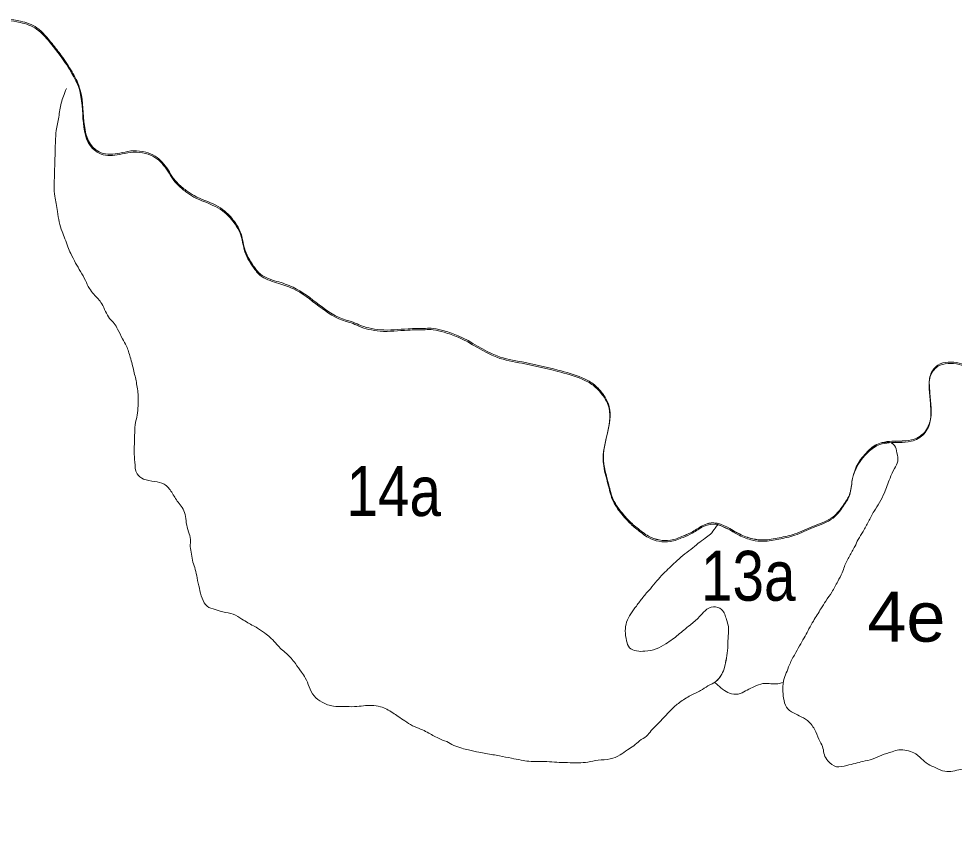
# Model space of a CAD drawing. Extents: x 854879 to 917879, y 8541948 to 8631048.
# Drawn here: x 882670 to 889796, y 8606564 to 8612725 of the extents above; entities that cross this region are included whole.
import ezdxf
from ezdxf.enums import TextEntityAlignment as Align

# ---------------------------------------------------------------- set-up
doc = ezdxf.new("R2010")
doc.units = 0
doc.header["$LTSCALE"] = 150
for name, color, linetype, lineweight in [('12', 7, 'Continuous', 13), ('40', 7, 'Continuous', 13), ('50', 7, 'Continuous', 13), ('59', 7, 'Continuous', 13)]:
    doc.layers.add(name, color=color, linetype=linetype, lineweight=lineweight)

msp = doc.modelspace()

# ---------------------------------------------------------------- linework, layer by layer
at = {"layer": '12'}
for points in [[(883458.2, 8611696.1), (883312.8, 8611690.2), (883254.5, 8611718.9), (883130.1, 8612194.4), (883075.4, 8612309.7), (882992.8, 8612435.6), (882922.5, 8612525.6), (882806.7, 8612646.7), (882682.3, 8612696.7), (882478.6, 8612709.3), (882317.4, 8612665.3), (882183, 8612509), (882088.6, 8612290.9), (882014.9, 8612093.1), (881954.6, 8611953.6), (881858.8, 8611827.3), (881770.9, 8611726.5), (881683.5, 8611663.8), (881605.9, 8611573), (881515, 8611428.8), (881452.8, 8611342.9), (881245.3, 8611256.2), (880823.3, 8611380.8), (880472, 8611369.8)], [(892672.9, 8609465.7), (892198, 8609621.7), (891998.2, 8609756.6), (891869.6, 8609877.9), (891760.9, 8609948), (891672, 8609974.5), (891475.1, 8609928.5), (891429, 8609908.6), (891359.8, 8609878.9), (891318.7, 8609853.9), (891241.9, 8609826.8), (891167.7, 8609799.7), (891085.8, 8609777.7), (890871.6, 8609770.1), (890792.6, 8609771), (890700.8, 8609772.1), (890588.7, 8609778.5), (890319.2, 8609835.3), (890207.7, 8609892.7), (889977.6, 8610050.9), (889903.9, 8610074.7), (889832.8, 8610093.4), (889748.7, 8610102), (889669.4, 8610077.5), (889612.4, 8610001.7), (889606.1, 8609899.9), (889615, 8609790.2), (889613.5, 8609665.3), (889566.5, 8609566.5), (889468.9, 8609509.1), (889374.5, 8609500), (889229, 8609483.9), (889139.1, 8609426.4), (889019.3, 8609216.3), (889000.1, 8609104.4), (888948.1, 8609010.8), (888873.1, 8608925), (888721.8, 8608852.9), (888580.9, 8608793.4), (888460.8, 8608764.3), (888340.7, 8608747.9), (888259.3, 8608756.5), (888157.7, 8608793.4), (887962.4, 8608877.3), (887885.8, 8608860.4), (887801, 8608810.4), (887731.8, 8608778.1), (887632, 8608746.2), (887466.7, 8608776.2), (887378.2, 8608841), (887340.3, 8608872), (887274.9, 8608941.6), (887197.2, 8609054.6), (887162.8, 8609167.2), (887122, 8609379.2), (887160, 8609783.9), (887115, 8609863.4), (887044.5, 8609935.6), (886960.9, 8609982.5), (886775.5, 8610040.8), (886503.5, 8610102.6), (886312.8, 8610148.2), (886016.4, 8610302.1), (885909.8, 8610339.1), (885825.9, 8610357.9), (885767.2, 8610358.6), (885634.6, 8610355.1), (885423, 8610347.5), (885336.5, 8610361.2), (885260.2, 8610385.1), (885201.9, 8610411.3), (885163.8, 8610421.9), (884758.9, 8610671.4), (884634.5, 8610716.2), (884510.2, 8610771.2), (884457.5, 8610833), (884387.7, 8610968.9), (884375.6, 8611025.1), (884356, 8611094.1), (884318.6, 8611160.8), (884238.1, 8611251), (884169.8, 8611295.1), (884004.9, 8611368.5), (883944.2, 8611407.4), (883908.9, 8611435.9), (883845.9, 8611502.9), (883805.9, 8611564.5), (883707.7, 8611670.2), (883636.7, 8611699), (883542.5, 8611710.4), (883458.2, 8611696.1)]]:
    msp.add_spline(points, degree=3, dxfattribs=at)
at = {"layer": '40'}
msp.add_line((887996.2, 8608876.2), (887978, 8608882.8), dxfattribs=at)
for points in [[(883033, 8612194.2), (883011.5, 8612135.1), (882994.2, 8612083.9), (882975.3, 8611977.1), (882956.5, 8611874.2), (882950, 8611791), (882948.3, 8611731.4), (882946.2, 8611664), (882944.3, 8611600.5), (882942.5, 8611536.9), (882939.8, 8611449.6), (882945.5, 8611374), (882955.6, 8611318.2), (882965.7, 8611258.4), (882979, 8611178.7), (883000.5, 8611106.7), (883022.5, 8611050.6), (883044.3, 8610990.5), (883066.4, 8610938.3), (883103.7, 8610866), (883141.1, 8610801.6), (883178.5, 8610733.2), (883208.2, 8610673), (883242.3, 8610628.5), (883303.2, 8610555.6), (883362.9, 8610443.1), (883397.2, 8610406.6), (883423.5, 8610362.3), (883460.7, 8610289.9), (883490.6, 8610233.6), (883519.6, 8610149.6), (883547.8, 8610041.7), (883568.6, 8609945.9), (883581.3, 8609842.3), (883579.4, 8609778.8), (883573.3, 8609707.5), (883559.9, 8609652.2), (883553.7, 8609576.8), (883551, 8609485.6), (883549.3, 8609430), (883554.8, 8609350.4), (883571.9, 8609262.7), (883621.9, 8609221.8), (883704.1, 8609204), (883778.3, 8609182.5), (883835.6, 8609121.6), (883884.5, 8609045), (883914.8, 8609004.6), (883936.9, 8608952.5), (883946.8, 8608888.7), (883964.5, 8608820.8), (883978.4, 8608760.9), (883976.9, 8608709.3), (883986.9, 8608649.5), (883997, 8608589.7), (884015, 8608533.7), (884028.8, 8608469.8), (884046.2, 8608390), (884067.5, 8608314), (884105.1, 8608253.6), (884167.4, 8608228.3), (884226, 8608211.1), (884304.2, 8608193.5), (884370.1, 8608156.2), (884416.5, 8608127.4), (884497.9, 8608081.8), (884555.8, 8608040.8), (884594.2, 8608008.1), (884636.2, 8607963.5), (884670.5, 8607927), (884709, 8607894.3), (884777.6, 8607817.3), (884822.9, 8607752.7), (884853.1, 8607708.3), (884882.6, 8607640.2), (884920, 8607571.8), (884981.5, 8607522.7), (885067.3, 8607493), (885146, 8607491.2), (885228.7, 8607489.3), (885295.9, 8607495.7), (885359, 8607498.3), (885425.7, 8607488.8), (885518.8, 8607443), (885561.3, 8607414.2), (885611.6, 8607381.3), (885669.5, 8607344.2), (885731.8, 8607319), (885782.3, 8607294), (885867.6, 8607248.4), (885929.9, 8607223.2)], [(883459.9, 8611706.3), (883314.5, 8611700.4), (883256.2, 8611729.2), (883131.8, 8612204.6), (883110.6, 8612253.5)], [(887978, 8608882.8), (887964.1, 8608887.6), (887887.5, 8608870.6), (887802.7, 8608820.7), (887733.5, 8608788.4), (887633.7, 8608756.5), (887468.4, 8608786.5), (887379.9, 8608851.2), (887342, 8608882.3), (887276.6, 8608951.8), (887198.9, 8609064.9), (887164.6, 8609177.4), (887123.7, 8609389.4), (887161.7, 8609794.2), (887116.7, 8609873.7), (887046.2, 8609945.9), (886962.6, 8609992.8), (886777.2, 8610051), (886505.2, 8610112.9), (886314.5, 8610158.5), (886018.1, 8610312.4), (885911.5, 8610349.3), (885827.6, 8610368.2), (885769, 8610368.9), (885636.3, 8610365.4), (885424.7, 8610357.7), (885338.2, 8610371.5), (885262, 8610395.3), (885203.6, 8610421.5), (885165.5, 8610432.2), (884760.6, 8610681.7), (884636.2, 8610726.5), (884512, 8610781.5), (884459.2, 8610843.3), (884389.4, 8610979.2), (884377.3, 8611035.4), (884357.7, 8611104.4), (884320.3, 8611171.1), (884239.8, 8611261.3), (884171.5, 8611305.4), (884006.6, 8611378.7), (883945.9, 8611417.7), (883910.6, 8611446.1), (883847.6, 8611513.1), (883807.6, 8611574.8), (883709.4, 8611680.4), (883638.4, 8611709.3), (883544.2, 8611720.6), (883459.9, 8611706.3)], [(890318.5, 8609846.4), (890209.4, 8609902.9), (889979.3, 8610061.1), (889905.6, 8610084.9), (889834.5, 8610103.6), (889750.4, 8610112.3), (889671.1, 8610087.8), (889614.1, 8610012), (889607.8, 8609910.1), (889616.7, 8609800.5), (889615.2, 8609675.6), (889568.2, 8609576.8), (889470.6, 8609519.3), (889376.2, 8609510.3), (889350.9, 8609507.7)], [(889319.9, 8609496.3), (889341.7, 8609477.2), (889359.8, 8609421.1), (889365.8, 8609357.4), (889340.5, 8609302.4), (889306.7, 8609227.7), (889264, 8609117.5), (889226.4, 8609042.9), (889185, 8608976.3), (889143.2, 8608897.8), (889101.6, 8608823.3), (889064.3, 8608760.6), (889039.1, 8608709.5), (888997.5, 8608635), (888959.7, 8608556.4), (888942.6, 8608509.1), (888909, 8608442.4), (888863.2, 8608360), (888817.9, 8608293.5), (888780.7, 8608234.8), (888722.8, 8608140.8), (888689.5, 8608081.9), (888660.3, 8608027), (888627, 8607968.2), (888589.6, 8607901.5), (888547.8, 8607823), (888522.3, 8607760.1), (888501, 8607704.9), (888490.6, 8607621.8), (888496.5, 8607554.1), (888518.1, 8607486.1), (888571.9, 8607441.2), (888630.1, 8607412.1), (888691.9, 8607370.9), (888741, 8607298.3), (888774.1, 8607222.1), (888796.3, 8607173.9), (888806.6, 8607122.1), (888832.9, 8607077.8), (888898.5, 8607032.6), (888977.6, 8607042.7), (889041.1, 8607057.2), (889100.6, 8607071.7), (889172, 8607089.9), (889243.8, 8607120.1), (889323.4, 8607146.1), (889375.1, 8607160.8), (889434, 8607155.5), (889488.6, 8607138.3), (889546.4, 8607093.3), (889596.4, 8607052.5), (889654.6, 8607023.4), (889724.8, 8606997.9), (889847.3, 8607011), (889906.3, 8607009.7), (889948, 8606953.2), (889954.2, 8606897.4), (889955.9, 8606821.9), (889950, 8606758.5), (889932.3, 8606691.4), (889930, 8606615.9), (889928.1, 8606552.4), (889951.7, 8606416.9), (889965.8, 8606360.9), (889983.9, 8606308.9), (890018, 8606264.4), (890071.7, 8606215.5), (890153.8, 8606193.8), (890213, 8606196.4), (890292.1, 8606206.6), (890347.3, 8606209.3), (890430.4, 8606223.3), (890488.2, 8606178.3), (890521.1, 8606094.1), (890527.2, 8606034.4), (890540.8, 8605962.6), (890550.6, 8605894.8), (890580.2, 8605830.6), (890598.3, 8605774.6), (890644.3, 8605733.8), (890706.6, 8605708.6), (890812.7, 8605698.2), (890899.9, 8605716.1), (890987.8, 8605757.8), (891047.8, 8605788.2), (891104, 8605822.7), (891152.4, 8605861.3), (891197, 8605904)], [(885929.9, 8607223.2), (885984.2, 8607194.1), (886046.6, 8607172.8), (886097.4, 8607159.8), (886175.6, 8607142.1), (886281.5, 8607123.8), (886332.4, 8607114.7), (886422.5, 8607096.8), (886496.9, 8607083.2), (886555.7, 8607073.9), (886630.5, 8607072.2), (886713.2, 8607070.3), (886787.9, 8607064.6), (886870.6, 8607062.8), (886933.6, 8607061.3), (887004.7, 8607067.7), (887083.9, 8607081.8), (887174.8, 8607091.6), (887250.5, 8607121.7), (887306.8, 8607160.1), (887355, 8607190.8), (887399.5, 8607229.5), (887451.7, 8607264.1), (887488.5, 8607306.9), (887541.3, 8607361.3), (887582, 8607404.1), (887639, 8607466.3), (887703.6, 8607520.5), (887788, 8607574.2), (887863.9, 8607612.2), (887920.1, 8607646.6), (887980.2, 8607681), (888025.2, 8607735.6), (888046.6, 8607790.7), (888060.4, 8607857.9), (888070.6, 8607937.1), (888072.3, 8607992.7), (888075.3, 8608095.9), (888061.3, 8608151.8), (888024.1, 8608228.1), (887961.8, 8608249.4), (887897.8, 8608219.1), (887853.1, 8608172.4), (887784.3, 8608110.4), (887735.8, 8608071.8), (887651, 8608002.3), (887598.8, 8607967.7), (887526.7, 8607929.6), (887439.5, 8607911.7), (887376.6, 8607913.2), (887322.2, 8607938.2), (887300.1, 8607990.4), (887290.5, 8608066.1), (887300.4, 8608133.4), (887374.9, 8608254.8), (887424.2, 8608321.2), (887481.3, 8608387.4), (887530.3, 8608445.9), (887579.2, 8608500.4), (887627.9, 8608546.9), (887672.5, 8608589.6), (887729.2, 8608640), (887789.6, 8608686.2), (887846.2, 8608732.6), (887898.5, 8608771.2), (887938.8, 8608802), (887975.7, 8608848.8), (887996.2, 8608876.2)]]:
    msp.add_spline(points, degree=3, dxfattribs=at)
at = {"layer": '50'}
msp.add_line((889316.9, 8609498.1), (889290.9, 8609501.3), dxfattribs=at)
for points in [[(883459.9, 8611706.3), (883314.5, 8611700.4), (883256.2, 8611729.2), (883131.8, 8612204.6), (883077.1, 8612320), (882994.5, 8612445.8), (882924.2, 8612535.8), (882808.4, 8612657), (882684, 8612706.9), (882480.2, 8612719.5), (882319.1, 8612675.6), (882184.7, 8612519.2), (882090.3, 8612301.2), (882016.6, 8612103.3), (881956.3, 8611963.9), (881860.5, 8611837.6), (881772.6, 8611736.7), (881685.2, 8611674.1), (881607.6, 8611583.3), (881516.7, 8611439.1), (881454.5, 8611353.2), (881247, 8611266.5), (880825, 8611391.1), (880473.7, 8611380.1)], [(892674.6, 8609475.9), (892199.7, 8609631.9), (891999.9, 8609766.8), (891871.3, 8609888.2), (891762.6, 8609958.2), (891673.7, 8609984.8), (891476.8, 8609938.7), (891430.7, 8609918.9), (891361.5, 8609889.2), (891320.4, 8609864.2), (891243.6, 8609837.1), (891169.4, 8609809.9), (891087.5, 8609787.9), (890873.3, 8609780.3), (890794.3, 8609781.3), (890702.5, 8609782.4), (890590.4, 8609788.8), (890320.9, 8609845.5), (890209.4, 8609902.9), (889979.3, 8610061.1), (889905.6, 8610084.9), (889834.5, 8610103.6), (889750.4, 8610112.3), (889671.1, 8610087.8), (889614.1, 8610012), (889607.8, 8609910.1), (889616.7, 8609800.5), (889615.2, 8609675.6), (889568.2, 8609576.8), (889470.6, 8609519.3), (889376.2, 8609510.3), (889230.7, 8609494.2), (889140.8, 8609436.7), (889021, 8609226.6), (889001.8, 8609114.7), (888949.8, 8609021), (888874.8, 8608935.3), (888723.5, 8608863.2), (888582.6, 8608803.7), (888462.5, 8608774.6), (888342.4, 8608758.2), (888261, 8608766.8), (888159.4, 8608803.7), (887964.1, 8608887.6), (887887.5, 8608870.6), (887802.7, 8608820.7), (887733.5, 8608788.4), (887633.7, 8608756.5), (887468.4, 8608786.5), (887379.9, 8608851.2), (887342, 8608882.3), (887276.6, 8608951.8), (887198.9, 8609064.9), (887164.6, 8609177.4), (887123.7, 8609389.4), (887161.7, 8609794.2), (887116.7, 8609873.7), (887046.2, 8609945.9), (886962.6, 8609992.8), (886777.2, 8610051), (886505.2, 8610112.9), (886314.5, 8610158.5), (886018.1, 8610312.4), (885911.5, 8610349.3), (885827.6, 8610368.2), (885769, 8610368.9), (885636.3, 8610365.4), (885424.7, 8610357.7), (885338.2, 8610371.5), (885262, 8610395.3), (885203.6, 8610421.5), (885165.5, 8610432.2), (884760.6, 8610681.7), (884636.2, 8610726.5), (884512, 8610781.5), (884459.2, 8610843.3), (884389.4, 8610979.2), (884377.3, 8611035.4), (884357.7, 8611104.4), (884320.3, 8611171.1), (884239.8, 8611261.3), (884171.5, 8611305.4), (884006.6, 8611378.7), (883945.9, 8611417.7), (883910.6, 8611446.1), (883847.6, 8611513.1), (883807.6, 8611574.8), (883709.4, 8611680.4), (883638.4, 8611709.3), (883544.2, 8611720.6), (883459.9, 8611706.3)], [(889290.9, 8609501.3), (889230.7, 8609494.2), (889140.8, 8609436.7), (889021, 8609226.6), (889001.8, 8609114.7), (888949.8, 8609021), (888874.8, 8608935.3), (888723.5, 8608863.2), (888582.6, 8608803.7), (888462.5, 8608774.6), (888342.4, 8608758.2), (888261, 8608766.8), (888159.4, 8608803.7), (887995, 8608876.4)], [(888492.8, 8607668.5), (888501, 8607704.9), (888522.3, 8607760.1), (888547.8, 8607823), (888589.6, 8607901.5), (888627, 8607968.2), (888660.3, 8608027), (888689.5, 8608081.9), (888722.8, 8608140.8), (888780.7, 8608234.8), (888817.9, 8608293.5), (888863.2, 8608360), (888909, 8608442.4), (888942.6, 8608509.1), (888959.7, 8608556.4), (888997.5, 8608635), (889039.1, 8608709.5), (889064.3, 8608760.6), (889101.6, 8608823.3), (889143.2, 8608897.8), (889185, 8608976.3), (889226.4, 8609042.9), (889264, 8609117.5), (889306.7, 8609227.7), (889340.5, 8609302.4), (889365.8, 8609357.4), (889359.8, 8609421.1), (889341.7, 8609477.2), (889316.9, 8609498.1)], [(887996.2, 8608876.2), (887975.7, 8608848.8), (887938.8, 8608802), (887898.5, 8608771.2), (887846.2, 8608732.6), (887789.6, 8608686.2), (887729.2, 8608640), (887672.5, 8608589.6), (887627.9, 8608546.9), (887579.2, 8608500.4), (887530.3, 8608445.9), (887481.3, 8608387.4), (887424.2, 8608321.2), (887374.9, 8608254.8), (887300.4, 8608133.4), (887290.5, 8608066.1), (887300.1, 8607990.4), (887322.2, 8607938.2), (887376.6, 8607913.2), (887439.5, 8607911.7), (887526.7, 8607929.6), (887598.8, 8607967.7), (887651, 8608002.3), (887735.8, 8608071.8), (887784.3, 8608110.4), (887853.1, 8608172.4), (887897.8, 8608219.1), (887961.8, 8608249.4), (888024.1, 8608228.1), (888061.3, 8608151.8), (888075.3, 8608095.9), (888072.3, 8607992.7), (888070.6, 8607937.1), (888060.4, 8607857.9), (888046.6, 8607790.7), (888025.2, 8607735.6), (887980.2, 8607681), (887966.5, 8607672.8)], [(887972.8, 8607674.2), (887995.2, 8607652.9), (888045.2, 8607612), (888099.6, 8607586.9), (888166.6, 8607589.4), (888218.6, 8607616), (888274.6, 8607642.6), (888338.3, 8607664.9), (888436.7, 8607662.7), (888493.5, 8607673.5)]]:
    msp.add_spline(points, degree=3, dxfattribs=at)

# ---------------------------------------------------------------- texts
at = {"layer": '59'}
for s, width, p in [('14a', 0.85, (885526.5, 8608940.3)), ('13a', 0.85, (888226.9, 8608295.6)), ('4e', 1.05, (889431.8, 8607984))]:
    msp.add_text(s, height=380, dxfattribs=dict(at, width=width)).set_placement(p, align=Align.CENTER)

doc.saveas('drawing.dxf')
